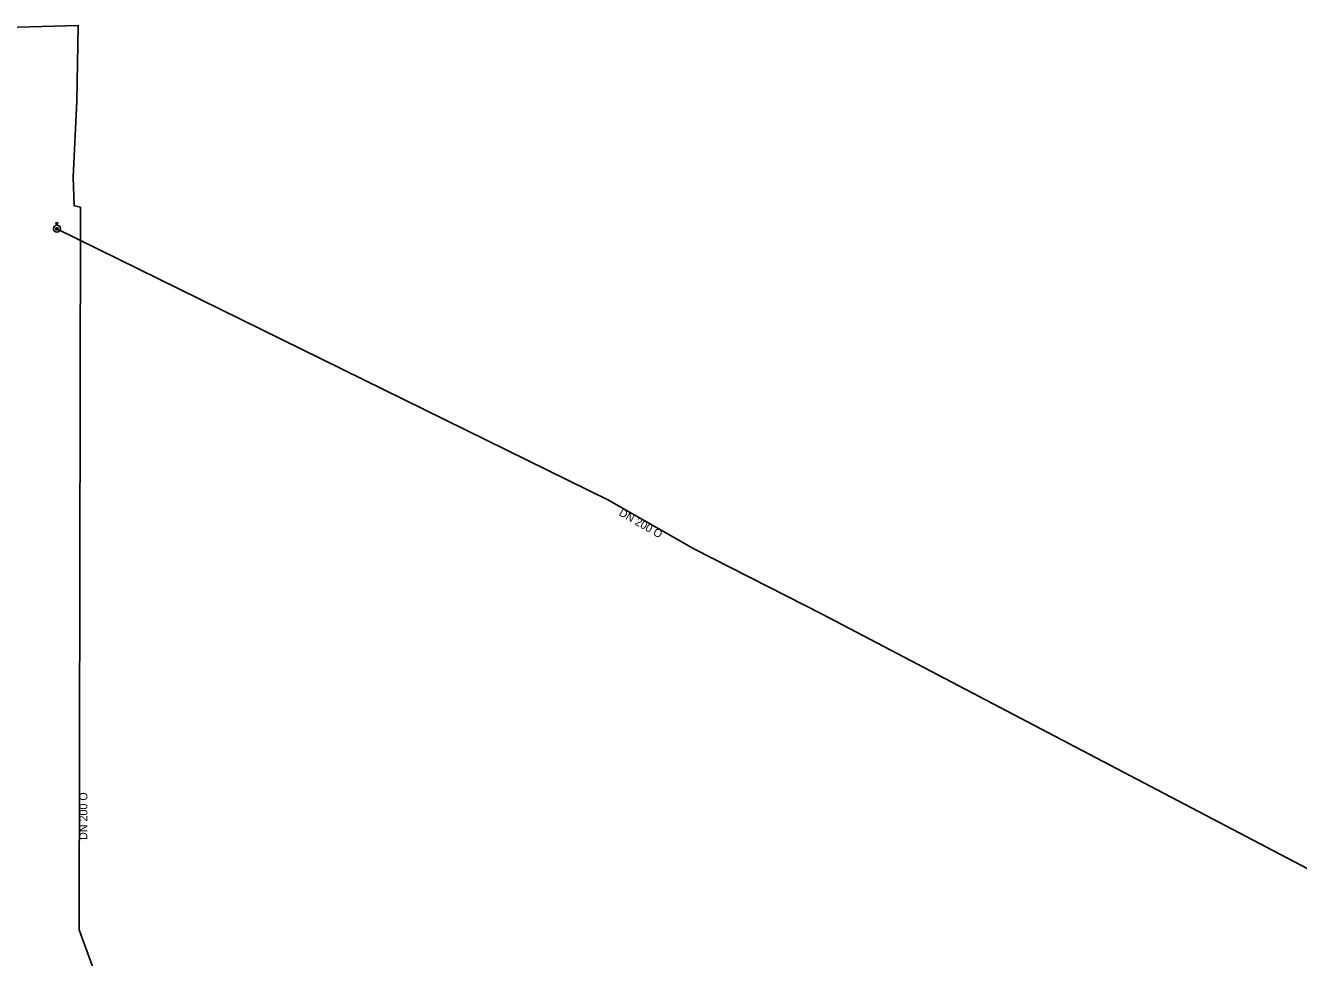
# Model space of a CAD drawing. Extents: x -491015 to -489994, y -1125687 to -1125176.
# Drawn here: x -490759.8 to -490504.5, y -1125419.4 to -1125232.5 of the extents above; entities that cross this region are included whole.
import ezdxf

# ---------------------------------------------------------------- set-up
doc = ezdxf.new("R2010")
doc.units = 0
for name, color, linetype in [('_voda_smvak_prevzato_z_dokumentace_', 7, 'Continuous'), ('Default', 7, 'Continuous'), ('MoLevel 30', 7, 'Continuous'), ('MoLevel 42', 7, 'Continuous'), ('MoLevel 46', 7, 'Continuous')]:
    doc.layers.add(name, color=color, linetype=linetype)

# ---------------------------------------------------------------- blocks, each defined once
blk = doc.blocks.new('_sachta_voda_')
at = {"layer": 'Default'}
blk.add_lwpolyline([(-0.01, 0.065), (0, 0.035), (0.01, 0.065)], dxfattribs=at)
blk.add_circle((0, 0), 0.035, dxfattribs=at)
blk = doc.blocks.new('_poklop_voda_')
at = {"layer": 'Default'}
blk.add_lwpolyline([(-0.02, 0.02), (0.02, 0.02), (0.02, -0.02), (-0.02, -0.02), (-0.02, 0.02)], dxfattribs=at)

msp = doc.modelspace()

# ---------------------------------------------------------------- linework, layer by layer
at = {"layer": '_voda_smvak_prevzato_z_dokumentace_'}
for points in [[(-490748.71, -1125268.96), (-490749.97, -1125268.7), (-490750.21, -1125262.93), (-490749.47, -1125247.72), (-490749.16, -1125232.51), (-490773.35, -1125233.17), (-490811.27, -1125234.19), (-490827.06, -1125234.84), (-490849.74, -1125235.78), (-490850.39, -1125250.92), (-490850.82, -1125257.39), (-490853.25, -1125257.28), (-490855.63, -1125257.21)], [(-490748.71, -1125268.96), (-490748.72, -1125270.45), (-490749, -1125413.83), (-490704.7, -1125535.33), (-490670.2, -1125619.59), (-490665.49, -1125631.59), (-490661.85, -1125640.89), (-490714.98, -1125658.08), (-490733.48, -1125664.06), (-490750.92, -1125669.7)], [(-490281.75, -1125517.39), (-490600.05, -1125350.51), (-490625.6, -1125337.53), (-490642.89, -1125327.65), (-490753.44, -1125273.25)]]:
    msp.add_lwpolyline(points, dxfattribs=at)

# ---------------------------------------------------------------- block references
at = {"layer": 'MoLevel 30', "xscale": 20, "yscale": 20}
msp.add_blockref('_sachta_voda_', (-490753.44, -1125273.25), dxfattribs=at)
at = {"layer": 'MoLevel 42', "xscale": 10, "yscale": 10}
msp.add_blockref('_poklop_voda_', (-490753.44, -1125273.25), dxfattribs=at)

# ---------------------------------------------------------------- texts
at = {"layer": 'MoLevel 46'}
for rotation, p in [(330.2551, (-490640.91, -1125330.63)), (89.8877, (-490747.36, -1125395.78))]:
    msp.add_text('DN 200 O', height=1.605, rotation=rotation, dxfattribs=at).set_placement(p)

doc.saveas('drawing.dxf')
